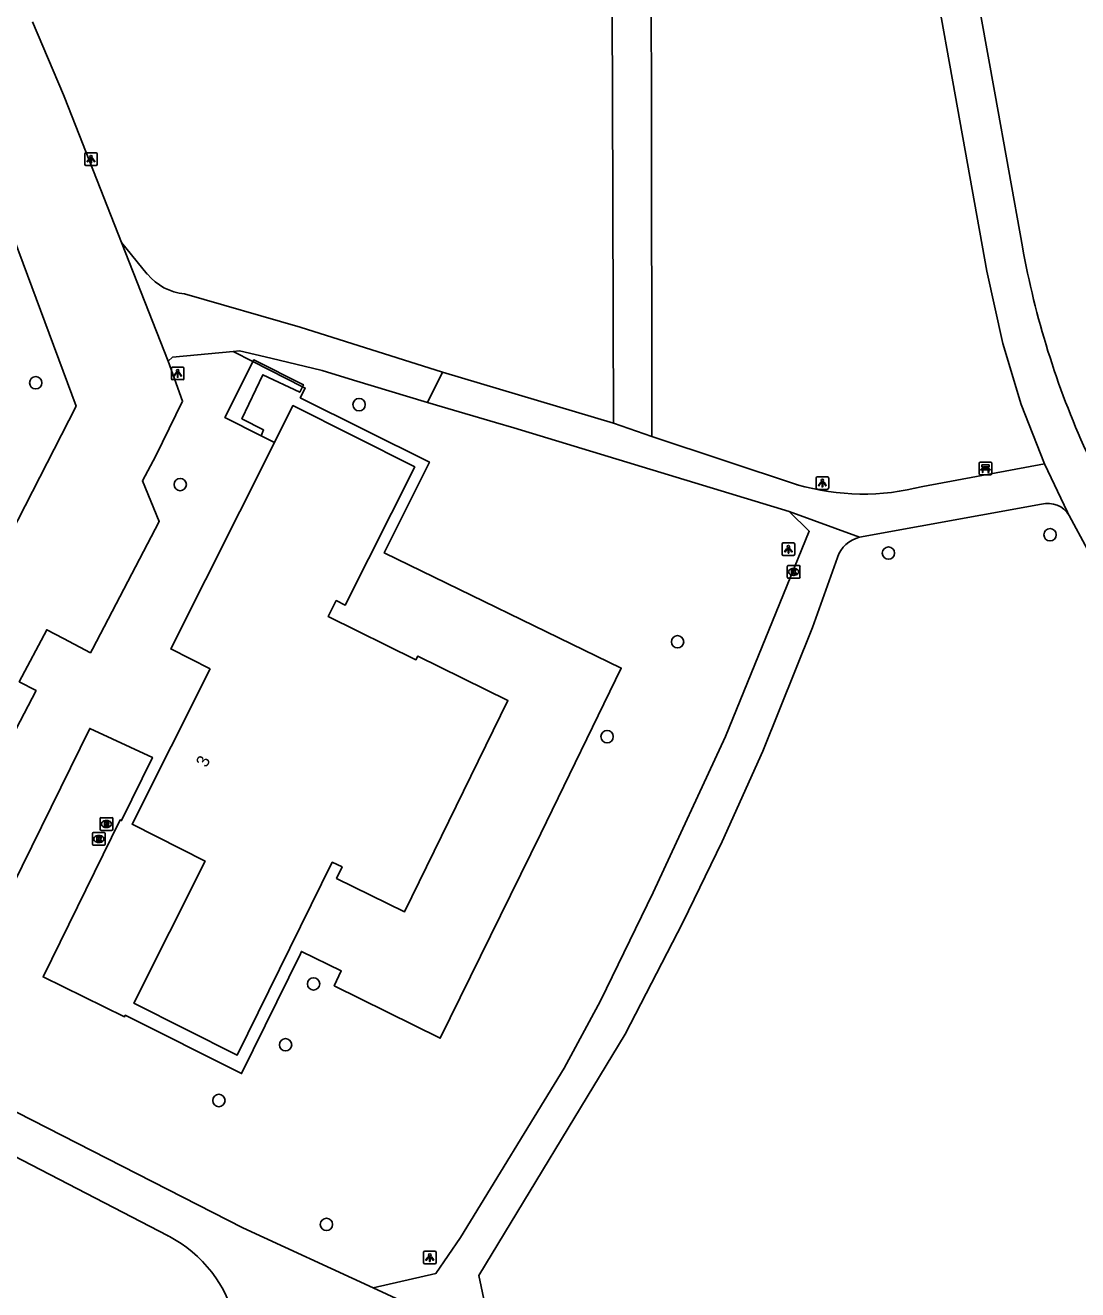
# Model space of a CAD drawing. Extents: x 162417 to 163721, y 384268 to 385416.
# Drawn here: x 162660.8 to 162744.1, y 384905.4 to 385005.5 of the extents above; entities that cross this region are included whole.
import ezdxf

# ---------------------------------------------------------------- set-up
doc = ezdxf.new("R2010")
doc.units = 0
for name, color, linetype in [('IMGEO_Bank', 7, 'Continuous'), ('IMGEO_Boom', 7, 'Continuous'), ('IMGEO_Groenvoorziening', 7, 'Continuous'), ('IMGEO_Haag', 7, 'Continuous'), ('IMGEO_Hek', 7, 'Continuous'), ('IMGEO_Kolk', 7, 'Continuous'), ('IMGEO_Lichtpunt', 7, 'Continuous'), ('IMGEO_Pand', 7, 'Continuous'), ('IMGEO_Pand_nummerreeks', 7, 'Continuous'), ('IMGEO_Rijbaan_lokaal_gesloten', 7, 'Continuous'), ('IMGEO_Rioolput', 7, 'Continuous'), ('IMGEO_Voetpad_gesloten', 7, 'Continuous'), ('IMGEO_Voetpad_halfverhard', 7, 'Continuous')]:
    doc.layers.add(name, color=color, linetype=linetype)

msp = doc.modelspace()

# ---------------------------------------------------------------- linework, layer by layer
at = {"layer": 'IMGEO_Bank'}
for p, q in [((162736.32, 384969.98), (162736.32, 384970.83)), ((162736.32, 384970.83), (162736.32, 384969.98)), ((162736.39, 384970.91), (162737.24, 384970.91)), ((162737.24, 384970.91), (162736.39, 384970.91)), ((162737.02, 384970.31), (162736.62, 384970.31)), ((162736.63, 384970.42), (162736.63, 384970.52)), ((162736.67, 384970.52), (162736.67, 384970.42)), ((162736.96, 384970.53), (162736.68, 384970.53)), ((162736.68, 384970.41), (162736.96, 384970.41)), ((162736.97, 384970.42), (162736.97, 384970.52)), ((162737.01, 384970.52), (162737.01, 384970.42)), ((162737.32, 384970.84), (162737.32, 384969.99)), ((162737.32, 384969.99), (162737.32, 384970.84)), ((162737.25, 384969.91), (162736.4, 384969.91)), ((162736.4, 384969.91), (162737.25, 384969.91))]:
    msp.add_line(p, q, dxfattribs=at)
for points in [[(162736.57, 384970.31), (162736.42, 384970.31), (162736.54, 384970.41), (162736.62, 384970.41)], [(162736.62, 384970.53), (162736.54, 384970.53), (162736.54, 384970.69), (162737.1, 384970.69), (162737.1, 384970.53), (162737.02, 384970.53)], [(162736.62, 384970.3), (162736.62, 384970.09), (162736.57, 384970.09), (162736.57, 384970.3)], [(162737.02, 384970.41), (162737.1, 384970.41), (162737.21, 384970.31), (162737.07, 384970.31)], [(162737.07, 384970.3), (162737.07, 384970.09), (162737.02, 384970.09), (162737.02, 384970.3)]]:
    msp.add_lwpolyline(points, dxfattribs=at)
for centre, radius, start, end in [((162736.4, 384970.83), 0.0779, 92.4484, 184.2845), ((162736.4, 384970.83), 0.0779, 92.4484, 184.2845), ((162736.57, 384970.3), 0.00671, 2.8957, 87.1043), ((162736.62, 384970.52), 0.00671, 2.8957, 87.1043), ((162736.62, 384970.42), 0.00671, 272.8957, 357.1043), ((162736.62, 384970.3), 0.00671, 92.8957, 177.1043), ((162736.68, 384970.52), 0.00671, 92.8957, 177.1043), ((162736.68, 384970.42), 0.00671, 182.8957, 267.1043), ((162736.96, 384970.52), 0.00671, 2.8957, 87.1043), ((162736.96, 384970.42), 0.00671, 272.8957, 357.1043), ((162737.02, 384970.52), 0.00671, 92.8957, 177.1043), ((162737.02, 384970.42), 0.00671, 182.8957, 267.1043), ((162737.02, 384970.3), 0.00671, 2.8957, 87.1043), ((162737.07, 384970.3), 0.00671, 92.8957, 177.1043), ((162737.24, 384970.83), 0.0779, 2.4484, 94.2845), ((162737.24, 384970.83), 0.0779, 2.4484, 94.2845), ((162736.4, 384969.99), 0.0779, 182.4484, 274.2845), ((162736.4, 384969.99), 0.0779, 182.4484, 274.2845), ((162737.24, 384969.99), 0.0779, 272.4484, 4.2845), ((162737.24, 384969.99), 0.0779, 272.4484, 4.2845)]:
    msp.add_arc(centre, radius, start, end, dxfattribs=at)
at = {"layer": 'IMGEO_Boom'}
for centre in [(162661.59, 384977.19), (162687.2, 384975.46), (162673.04, 384969.13), (162741.93, 384965.16), (162729.13, 384963.71), (162712.43, 384956.68), (162706.85, 384949.17), (162683.6, 384929.59), (162681.38, 384924.77), (162676.1, 384920.36), (162684.62, 384910.55)]:
    msp.add_circle(centre, 0.489, dxfattribs=at)
at = {"layer": 'IMGEO_Groenvoorziening'}
for points in [[(162678.79, 384978.87), (162677.22, 384979.67)], [(162682.72, 384976.88), (162678.79, 384978.87)], [(162654.1, 384938.33), (162658.98, 384935.79), (162665.87, 384949.82), (162670.83, 384947.53), (162668.39, 384942.52), (162668.28, 384942.58), (162662.17, 384930.15), (162668.62, 384926.98), (162668.68, 384927.11), (162677.9, 384922.49), (162682.57, 384931.96), (162682.64, 384932.16), (162685.79, 384930.62), (162685.24, 384929.45), (162693.63, 384925.29), (162701.61, 384941.49), (162707.97, 384954.6), (162689.2, 384963.72), (162692.78, 384970.91), (162682.55, 384976.01), (162682.94, 384976.77), (162682.72, 384976.88)]]:
    msp.add_lwpolyline(points, dxfattribs=at)
at = {"layer": 'IMGEO_Haag'}
for points in [[(162678.79, 384978.87), (162676.57, 384974.45), (162679.45, 384973), (162679.64, 384973.46), (162677.92, 384974.35), (162679.58, 384977.83), (162682.5, 384976.44), (162682.72, 384976.88)], [(162682.72, 384976.88), (162682.79, 384977.03), (162678.86, 384979), (162678.79, 384978.87)]]:
    msp.add_lwpolyline(points, dxfattribs=at)
at = {"layer": 'IMGEO_Hek'}
for points in [[(162682.5, 384976.44), (162682.79, 384977.03), (162678.86, 384979), (162676.57, 384974.45), (162679.45, 384973)], [(162679.45, 384973), (162680.5, 384972.47)]]:
    msp.add_lwpolyline(points, dxfattribs=at)
at = {"layer": 'IMGEO_Kolk'}
for p, q in [((162721.12, 384961.79), (162721.12, 384962.64)), ((162721.2, 384962.72), (162722.05, 384962.72)), ((162721.61, 384962.5), (162721.64, 384962.5)), ((162722.12, 384962.64), (162722.12, 384961.79)), ((162722.05, 384961.72), (162721.2, 384961.72)), ((162721.63, 384961.94), (162721.61, 384961.94))]:
    msp.add_line(p, q, dxfattribs=at)
for points in [[(162721.12, 384961.79), (162721.12, 384962.64)], [(162721.2, 384962.72), (162722.05, 384962.72)], [(162721.44, 384962.42), (162721.57, 384962.42), (162721.57, 384962.26), (162721.7, 384962.42), (162721.86, 384962.42), (162721.71, 384962.27), (162721.87, 384962.02), (162721.71, 384962.02), (162721.63, 384962.18), (162721.57, 384962.11), (162721.57, 384962.02), (162721.44, 384962.02), (162721.44, 384962.42)], [(162722.12, 384962.64), (162722.12, 384961.79)], [(162722.05, 384961.72), (162721.2, 384961.72)]]:
    msp.add_lwpolyline(points, dxfattribs=at)
for centre, start, end in [((162721.2, 384962.64), 91.552, 178.448), ((162721.2, 384962.64), 91.552, 178.448), ((162722.05, 384962.64), 1.552, 88.448), ((162722.05, 384962.64), 1.552, 88.448), ((162721.2, 384961.79), 181.552, 268.448), ((162721.2, 384961.79), 181.552, 268.448), ((162722.05, 384961.79), 271.552, 358.448), ((162722.05, 384961.79), 271.552, 358.448)]:
    msp.add_arc(centre, 0.0765, start, end, dxfattribs=at)
for centre, major_axis, ratio, start_param, end_param in [((162721.61, 384962.22), (-0.387, 0.002), 0.722429, 4.712389, 7.853982), ((162721.63, 384962.22), (-0.39, 0.002), 0.717154, 1.570796, 4.712389)]:
    msp.add_ellipse(centre, major_axis=major_axis, ratio=ratio, start_param=start_param, end_param=end_param, dxfattribs=at)
at = {"layer": 'IMGEO_Lichtpunt'}
for p, q in [((162665.47, 384995.31), (162665.47, 384994.5)), ((162665.47, 384995.31), (162665.47, 384994.5)), ((162666.37, 384995.4), (162665.57, 384995.4)), ((162666.37, 384995.4), (162665.57, 384995.4)), ((162666.47, 384994.5), (162666.47, 384995.31)), ((162666.47, 384994.5), (162666.47, 384995.31)), ((162665.57, 384994.4), (162666.37, 384994.4)), ((162665.57, 384994.4), (162666.37, 384994.4)), ((162672.34, 384978.34), (162672.34, 384977.53)), ((162672.34, 384978.34), (162672.34, 384977.53)), ((162673.24, 384978.43), (162672.43, 384978.43)), ((162673.24, 384978.43), (162672.43, 384978.43)), ((162673.33, 384977.53), (162673.33, 384978.34)), ((162673.33, 384977.53), (162673.33, 384978.34)), ((162672.43, 384977.44), (162673.24, 384977.44)), ((162672.43, 384977.44), (162673.24, 384977.44)), ((162723.4, 384969.66), (162723.4, 384968.85)), ((162723.4, 384969.66), (162723.4, 384968.85)), ((162724.3, 384969.75), (162723.5, 384969.75)), ((162724.3, 384969.75), (162723.5, 384969.75)), ((162724.4, 384968.85), (162724.4, 384969.66)), ((162724.4, 384968.85), (162724.4, 384969.66)), ((162723.5, 384968.75), (162724.3, 384968.75)), ((162723.5, 384968.75), (162724.3, 384968.75)), ((162720.71, 384964.42), (162720.71, 384963.61)), ((162720.71, 384964.42), (162720.71, 384963.61)), ((162721.61, 384964.51), (162720.8, 384964.51)), ((162721.61, 384964.51), (162720.8, 384964.51)), ((162721.71, 384963.61), (162721.71, 384964.42)), ((162721.71, 384963.61), (162721.71, 384964.42)), ((162720.8, 384963.52), (162721.61, 384963.52)), ((162720.8, 384963.52), (162721.61, 384963.52)), ((162692.31, 384908.33), (162692.31, 384907.52)), ((162692.31, 384908.33), (162692.31, 384907.52)), ((162693.21, 384908.43), (162692.4, 384908.43)), ((162693.21, 384908.43), (162692.4, 384908.43)), ((162693.3, 384907.52), (162693.3, 384908.33)), ((162693.3, 384907.52), (162693.3, 384908.33)), ((162692.4, 384907.43), (162693.21, 384907.43)), ((162692.4, 384907.43), (162693.21, 384907.43))]:
    msp.add_line(p, q, dxfattribs=at)
for points in [[(162665.85, 384994.97), (162665.89, 384994.94), (162665.7, 384994.68), (162665.66, 384994.71), (162665.85, 384994.97)], [(162665.95, 384994.92), (162666, 384994.92), (162666, 384994.6), (162665.95, 384994.6), (162665.95, 384994.92)], [(162666.06, 384994.94), (162666.1, 384994.97), (162666.28, 384994.71), (162666.25, 384994.68), (162666.06, 384994.94)], [(162672.71, 384978), (162672.75, 384977.97), (162672.56, 384977.71), (162672.52, 384977.74), (162672.71, 384978)], [(162672.81, 384977.95), (162672.86, 384977.95), (162672.86, 384977.63), (162672.81, 384977.63), (162672.81, 384977.95)], [(162672.92, 384977.97), (162672.96, 384978), (162673.15, 384977.74), (162673.11, 384977.71), (162672.92, 384977.97)], [(162723.78, 384969.32), (162723.81, 384969.29), (162723.63, 384969.03), (162723.59, 384969.06), (162723.78, 384969.32)], [(162723.88, 384969.27), (162723.93, 384969.27), (162723.93, 384968.95), (162723.88, 384968.95), (162723.88, 384969.27)], [(162723.99, 384969.29), (162724.03, 384969.32), (162724.21, 384969.06), (162724.17, 384969.03), (162723.99, 384969.29)], [(162721.08, 384964.08), (162721.12, 384964.05), (162720.94, 384963.79), (162720.9, 384963.82), (162721.08, 384964.08)], [(162721.19, 384964.03), (162721.23, 384964.03), (162721.23, 384963.71), (162721.19, 384963.71), (162721.19, 384964.03)], [(162721.3, 384964.05), (162721.33, 384964.08), (162721.52, 384963.82), (162721.48, 384963.79), (162721.3, 384964.05)], [(162692.68, 384907.99), (162692.72, 384907.97), (162692.53, 384907.7), (162692.49, 384907.73), (162692.68, 384907.99)], [(162692.78, 384907.95), (162692.83, 384907.95), (162692.83, 384907.62), (162692.78, 384907.62), (162692.78, 384907.95)], [(162692.89, 384907.97), (162692.93, 384907.99), (162693.12, 384907.73), (162693.08, 384907.7), (162692.89, 384907.97)]]:
    msp.add_lwpolyline(points, dxfattribs=at)
for centre in [(162665.97, 384995.1), (162672.84, 384978.14), (162723.9, 384969.45), (162721.21, 384964.22), (162692.81, 384908.13)]:
    msp.add_circle(centre, 0.0994, dxfattribs=at)
for centre, start, end in [((162665.57, 384995.31), 90, 180), ((162665.57, 384995.31), 90, 180), ((162666.37, 384995.31), 0, 90), ((162666.37, 384995.31), 0, 90), ((162665.57, 384994.5), 180, 270), ((162665.57, 384994.5), 180, 270), ((162666.37, 384994.5), 270, 0), ((162666.37, 384994.5), 270, 360), ((162672.43, 384978.34), 90, 180), ((162672.43, 384978.34), 90, 180), ((162673.24, 384978.34), 0, 90), ((162673.24, 384978.34), 0, 90), ((162672.43, 384977.53), 180, 270), ((162672.43, 384977.53), 180, 270), ((162673.24, 384977.53), 270, 0), ((162673.24, 384977.53), 270, 360), ((162723.5, 384969.66), 90, 180), ((162723.5, 384969.66), 90, 180), ((162724.3, 384969.66), 0, 90), ((162724.3, 384969.66), 0, 90), ((162723.5, 384968.85), 180, 270), ((162723.5, 384968.85), 180, 270), ((162724.3, 384968.85), 270, 0), ((162724.3, 384968.85), 270, 360), ((162720.8, 384964.42), 90, 180), ((162720.8, 384964.42), 90, 180), ((162721.61, 384964.42), 0, 90), ((162721.61, 384964.42), 0, 90), ((162720.8, 384963.61), 180, 270), ((162720.8, 384963.61), 180, 270), ((162721.61, 384963.61), 270, 0), ((162721.61, 384963.61), 270, 360), ((162692.4, 384908.33), 90, 180), ((162692.4, 384908.33), 90, 180), ((162693.21, 384908.33), 0, 90), ((162693.21, 384908.33), 0, 90), ((162692.4, 384907.52), 180, 270), ((162692.4, 384907.52), 180, 270), ((162693.21, 384907.52), 270, 0), ((162693.21, 384907.52), 270, 360)]:
    msp.add_arc(centre, 0.0946, start, end, dxfattribs=at)
at = {"layer": 'IMGEO_Pand'}
msp.add_lwpolyline([(162675.41, 384954.55), (162672.29, 384956.12), (162680.5, 384972.47), (162681.96, 384975.38), (162691.61, 384970.53), (162686.11, 384959.59), (162685.4, 384959.95), (162684.76, 384958.68), (162691.71, 384955.26), (162691.85, 384955.55), (162698.99, 384952.03), (162690.81, 384935.31), (162685.42, 384937.95), (162685.86, 384938.85), (162685.08, 384939.23), (162677.56, 384923.95), (162669.36, 384928.07), (162675.01, 384939.32), (162669.22, 384942.23), (162675.41, 384954.55)], dxfattribs=at)
at = {"layer": 'IMGEO_Rijbaan_lokaal_gesloten'}
for points in [[(162732.26, 385011.89), (162707.78, 385009.81), (162701.77, 385013.3), (162700.13, 385010.54), (162707.26, 385006.25), (162707.27, 385000), (162707.35, 384973.99)], [(162732.85, 385008.69), (162710.35, 385006.75), (162710.37, 385000), (162710.38, 384972.94)], [(162668.38, 384988.3), (162663.91, 384999.73), (162663.79, 385000), (162661.34, 385005.78)], [(162655.13, 385001.31), (162655.62, 385000), (162664.79, 384975.34), (162641.1, 384929.12)], [(162668.38, 384988.3), (162672.08, 384978.9)], [(162670.43, 384985.8), (162668.38, 384988.3)], [(162693.81, 384978.04), (162682.55, 384981.59), (162673.38, 384984.24)], [(162677.22, 384979.67), (162672.42, 384979.21), (162672.08, 384978.9)], [(162677.22, 384979.67), (162677.72, 384979.72), (162680.21, 384979.14), (162684.29, 384978.17), (162686.77, 384977.41), (162692.63, 384975.64)], [(162672.08, 384978.9), (162673.23, 384975.73), (162671.1, 384971.41), (162670.04, 384969.43), (162671.38, 384966.22), (162666.08, 384956.11), (162665.93, 384955.82), (162663.79, 384956.94), (162662.46, 384957.64), (162660.29, 384953.52), (162661.62, 384952.82), (162657.16, 384944.33), (162656.47, 384943.01), (162654.1, 384938.33)], [(162692.63, 384975.64), (162693.81, 384978.04)], [(162707.35, 384973.99), (162693.81, 384978.04)], [(162721.28, 384967), (162699.47, 384973.62), (162698.02, 384974.05), (162693.79, 384975.29), (162692.63, 384975.64)], [(162707.35, 384973.99), (162710.38, 384972.94)], [(162710.38, 384972.94), (162721.92, 384969.12)], [(162731.85, 384968.99), (162741.48, 384970.77)], [(162741.48, 384970.77), (162743.32, 384966.95), (162743.45, 384966.69)], [(162726.84, 384964.96), (162741.25, 384967.58)], [(162726.84, 384964.96), (162721.28, 384967)]]:
    msp.add_lwpolyline(points, dxfattribs=at)
for centre, radius, start, end in [((162673.73, 384988.47), 4.24, 218.9757, 265.3474), ((162727.12, 384986.99), 18.61, 253.7476, 284.7066), ((162741.75, 384965.65), 1.99, 31.4464, 104.7445)]:
    msp.add_arc(centre, radius, start, end, dxfattribs=at)
at = {"layer": 'IMGEO_Rioolput'}
for p, q in [((162666.69, 384941.83), (162666.69, 384942.68)), ((162666.77, 384942.75), (162667.62, 384942.75)), ((162667.18, 384942.53), (162667.21, 384942.53)), ((162667.69, 384942.68), (162667.69, 384941.83)), ((162666.09, 384940.65), (162666.09, 384941.5)), ((162666.16, 384941.58), (162667.02, 384941.58)), ((162666.58, 384941.35), (162666.6, 384941.35)), ((162667.62, 384941.75), (162666.77, 384941.75)), ((162667.09, 384941.5), (162667.09, 384940.65)), ((162667.2, 384941.97), (162667.18, 384941.97)), ((162667.02, 384940.57), (162666.16, 384940.57)), ((162666.6, 384940.8), (162666.57, 384940.8))]:
    msp.add_line(p, q, dxfattribs=at)
for points in [[(162666.69, 384941.83), (162666.69, 384942.68)], [(162666.77, 384942.75), (162667.62, 384942.75)], [(162667.28, 384942.45), (162667.03, 384942.45), (162667.03, 384942.05)], [(162667.03, 384942.05), (162667.15, 384942.05), (162667.15, 384942.22), (162667.17, 384942.22)], [(162667.21, 384942.37), (162667.15, 384942.37), (162667.15, 384942.29)], [(162667.15, 384942.29), (162667.21, 384942.29)], [(162667.21, 384942.19), (162667.28, 384942.05), (162667.42, 384942.05), (162667.36, 384942.18)], [(162667.69, 384942.68), (162667.69, 384941.83)], [(162666.09, 384940.65), (162666.09, 384941.5)], [(162666.16, 384941.58), (162667.02, 384941.58)], [(162666.68, 384941.27), (162666.42, 384941.27), (162666.42, 384940.87)], [(162666.6, 384941.19), (162666.55, 384941.19), (162666.55, 384941.11)], [(162667.62, 384941.75), (162666.77, 384941.75)], [(162667.09, 384941.5), (162667.09, 384940.65)], [(162667.02, 384940.57), (162666.16, 384940.57)], [(162666.42, 384940.87), (162666.55, 384940.87), (162666.55, 384941.04), (162666.56, 384941.04)], [(162666.55, 384941.11), (162666.6, 384941.11)], [(162666.61, 384941.01), (162666.68, 384940.87), (162666.82, 384940.87), (162666.75, 384941)]]:
    msp.add_lwpolyline(points, dxfattribs=at)
for centre, radius, start, end in [((162666.77, 384942.68), 0.0765, 91.552, 178.448), ((162666.77, 384942.68), 0.0765, 91.552, 178.448), ((162667.16, 384942.16), 0.0533, 26.0293, 88.6989), ((162667.21, 384942.28), 0.0964, 77.0061, 93.1865), ((162667.19, 384942.48), 0.19, 274.7715, 282.9687), ((162667.23, 384942.33), 0.0378, 276.6634, 79.6772), ((162667.28, 384942.34), 0.109, 350.3612, 89.416), ((162667.28, 384942.34), 0.112, 277.5842, 350.9817), ((162667.26, 384942.13), 0.108, 29.5134, 73.7905), ((162667.62, 384942.68), 0.0765, 1.552, 88.448), ((162667.62, 384942.68), 0.0765, 1.552, 88.448), ((162666.16, 384941.5), 0.0765, 91.552, 178.448), ((162666.16, 384941.5), 0.0765, 91.552, 178.448), ((162666.61, 384941.1), 0.0964, 77.0061, 93.1865), ((162666.62, 384941.15), 0.0378, 276.6634, 79.6772), ((162666.68, 384941.16), 0.109, 350.3612, 89.416), ((162666.77, 384941.83), 0.0765, 181.552, 268.448), ((162666.77, 384941.83), 0.0765, 181.552, 268.448), ((162667.01, 384941.5), 0.0765, 1.552, 88.448), ((162667.01, 384941.5), 0.0765, 1.552, 88.448), ((162667.62, 384941.83), 0.0765, 271.552, 358.448), ((162667.62, 384941.83), 0.0765, 271.552, 358.448), ((162666.16, 384940.65), 0.0765, 181.552, 268.448), ((162666.16, 384940.65), 0.0765, 181.552, 268.448), ((162666.56, 384940.98), 0.0533, 26.0293, 88.6989), ((162666.59, 384941.3), 0.19, 274.7715, 282.9687), ((162666.67, 384941.16), 0.112, 277.5842, 350.9817), ((162666.66, 384940.95), 0.108, 29.5134, 73.7905), ((162667.01, 384940.65), 0.0765, 271.552, 358.448), ((162667.01, 384940.65), 0.0765, 271.552, 358.448)]:
    msp.add_arc(centre, radius, start, end, dxfattribs=at)
for centre, major_axis, ratio, start_param, end_param in [((162667.18, 384942.25), (-0.387, 0.002), 0.722429, 4.712389, 7.853982), ((162667.2, 384942.25), (-0.39, 0.002), 0.717154, 1.570796, 4.712389), ((162666.58, 384941.07), (-0.387, 0.002), 0.722429, 4.712389, 7.853982), ((162666.6, 384941.07), (-0.39, 0.002), 0.717154, 1.570796, 4.712389)]:
    msp.add_ellipse(centre, major_axis=major_axis, ratio=ratio, start_param=start_param, end_param=end_param, dxfattribs=at)
at = {"layer": 'IMGEO_Voetpad_gesloten'}
for points in [[(162648.25, 384926.74), (162649.36, 384924.91), (162677.99, 384910.27), (162688.32, 384905.52)], [(162672.07, 384909.65), (162657.64, 384917.1)], [(162688.32, 384905.52), (162694.07, 384902.87)]]:
    msp.add_lwpolyline(points, dxfattribs=at)
for centre, radius, start, end in [((162667.11, 384900.12), 10.74, 56.1084, 62.5204), ((162667.26, 384900.36), 10.46, 7.4117, 56.0594)]:
    msp.add_arc(centre, radius, start, end, dxfattribs=at)
at = {"layer": 'IMGEO_Voetpad_halfverhard'}
for points in [[(162727.1, 385058.13), (162735.23, 385012.67), (162740.32, 385012.68), (162741.13, 385009.58), (162735.87, 385009.49), (162737.58, 385000), (162739.74, 384987.97)], [(162741.48, 384970.77), (162739.64, 384975.48), (162738.18, 384980.29), (162736.92, 384986.02), (162734.41, 385000), (162732.85, 385008.69)], [(162688.32, 384905.52), (162693.29, 384906.67), (162695.24, 384909.51), (162703.45, 384922.91), (162706.32, 384928.26), (162710.49, 384936.83), (162716.22, 384949.19), (162722.86, 384965.43), (162721.28, 384967)], [(162743.45, 384966.69), (162749.25, 384955.92), (162751.44, 384951.87), (162758.92, 384936.29), (162760.4, 384932.9), (162765.08, 384920.8), (162766.45, 384916.8)], [(162697.82, 384901.15), (162696.7, 384906.49), (162708.29, 384925.61), (162712.85, 384934.46), (162715.96, 384940.88), (162719.18, 384948.02), (162723.12, 384957.81), (162725.09, 384963.37)]]:
    msp.add_lwpolyline(points, dxfattribs=at)
for centre, radius, start, end in [((162807.07, 385000.05), 68.4, 190.1722, 204.4539), ((162727.49, 384962.49), 2.56, 104.7599, 159.9697)]:
    msp.add_arc(centre, radius, start, end, dxfattribs=at)

# ---------------------------------------------------------------- texts
at = {"layer": 'IMGEO_Pand_nummerreeks'}
msp.add_text('3', height=1, rotation=63.3405, dxfattribs=at).set_placement((162675.12, 384946.67))

doc.saveas('drawing.dxf')
